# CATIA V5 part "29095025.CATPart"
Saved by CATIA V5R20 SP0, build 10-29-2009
Part number: 29095025
Definition: NONE
Nomenclature: 29095025
Source: Unknown
Description: 29095025
Bounding box of the stored display mesh (mm): x -12.5 to 44.548, y -61.5 to 96.048, z -51.5 to 51.5
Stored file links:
  C:\Users\Utente\Desktop\IO LAVORO\3D X SITO CF\X SITO\PLASTICA\RF1\29095025.CATPart
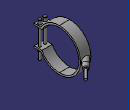
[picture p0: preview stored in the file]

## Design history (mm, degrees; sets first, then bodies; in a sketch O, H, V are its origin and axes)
Body1 "29095025" (main body)
  Solid1: solid without history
